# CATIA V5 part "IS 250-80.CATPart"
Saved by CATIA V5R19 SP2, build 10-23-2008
Part number: IS 250-80
Bounding box of the stored display mesh (mm): x -18.951 to 18.951, y -18.952 to 18.952, z 0 to 210
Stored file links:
  C:\Users\Bora\Desktop\3D Katı model\IS serisi\IS 250\IS 250-80.CATPart
  C:\Program Files\Dassault Systemes\B19\intel_a\reffiles\standard\MetricThickPitch.txt
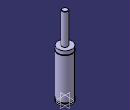
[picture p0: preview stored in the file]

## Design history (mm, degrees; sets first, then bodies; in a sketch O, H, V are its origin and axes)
Body1 (main body)
  Sketch1 on yz-plane, origin (0, 0, 0), H (0, 1, 0), V (0, 0, 1)
    point P3 (7.5, 209)
    point P5 (7.5, 209)
    point P7 (19, 118.5)
    point P8 (19, 116.5)
    point P12 (19, 116.5)
    point P13 (19, 118.5)
    line L1 (19, 0) -> (19, 4)
    line L2 (7.5, 209) -> (7.5, 128)
    arc A1 centre (6.5, 209) radius 1 from (7.5, 209) to (6.5, 210) ccw
    arc A2 centre (19, 117.5) radius 1 from (19, 118.5) to (19, 116.5) ccw
    line L3 (16.5, 7.5) -> (16.5, 4)
    line L4 (19, 7.5) -> (19, 116.5)
    line L5 (19, 118.5) -> (19, 128)
    line L6 (6.5, 210) -> (0, 210)
    point P15 (0, 210)
    line L7 (7.5, 128) -> (19, 128)
    line L8 (16.5, 7.5) -> (19, 7.5)
    line L9 (16.5, 4) -> (19, 4)
    line L10 (0, 0) -> (19, 0)
    coincidence: P15 V, P3 P5, P7 P13, P8 P12
    tangency: L6 A1
    horizontal: L7 H, L8 H, L9 H, L10 H
  Shaft1: profile Sketch1, axis Sketch1.V, angle 360
  Sketch2 on xy-plane, origin (-7.9865, 7.9865, 0), H (1, 0, 0), V (0, 1, 0)
    point P1 (0, 0)
  Hole1: placed by Sketch2, at (-7.9865, 7.9865, 0) direction (0, 0, -1), diameter 6.647, depth 7, threaded "M8", thread diameter 8, thread depth 7, pitch 1.25
  Sketch3 on face of Shaft1 from Sketch1.L10, origin (0, 0, 0), H (1, 0, 0), V (0, -1, 0)
    point P1 (0, 0)
  Hole2: placed by Sketch3, at (0, 0, 0) direction (0, 0, 1), diameter 6.647, depth 7, threaded "M8", thread diameter 8, thread depth 7, pitch 1.25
